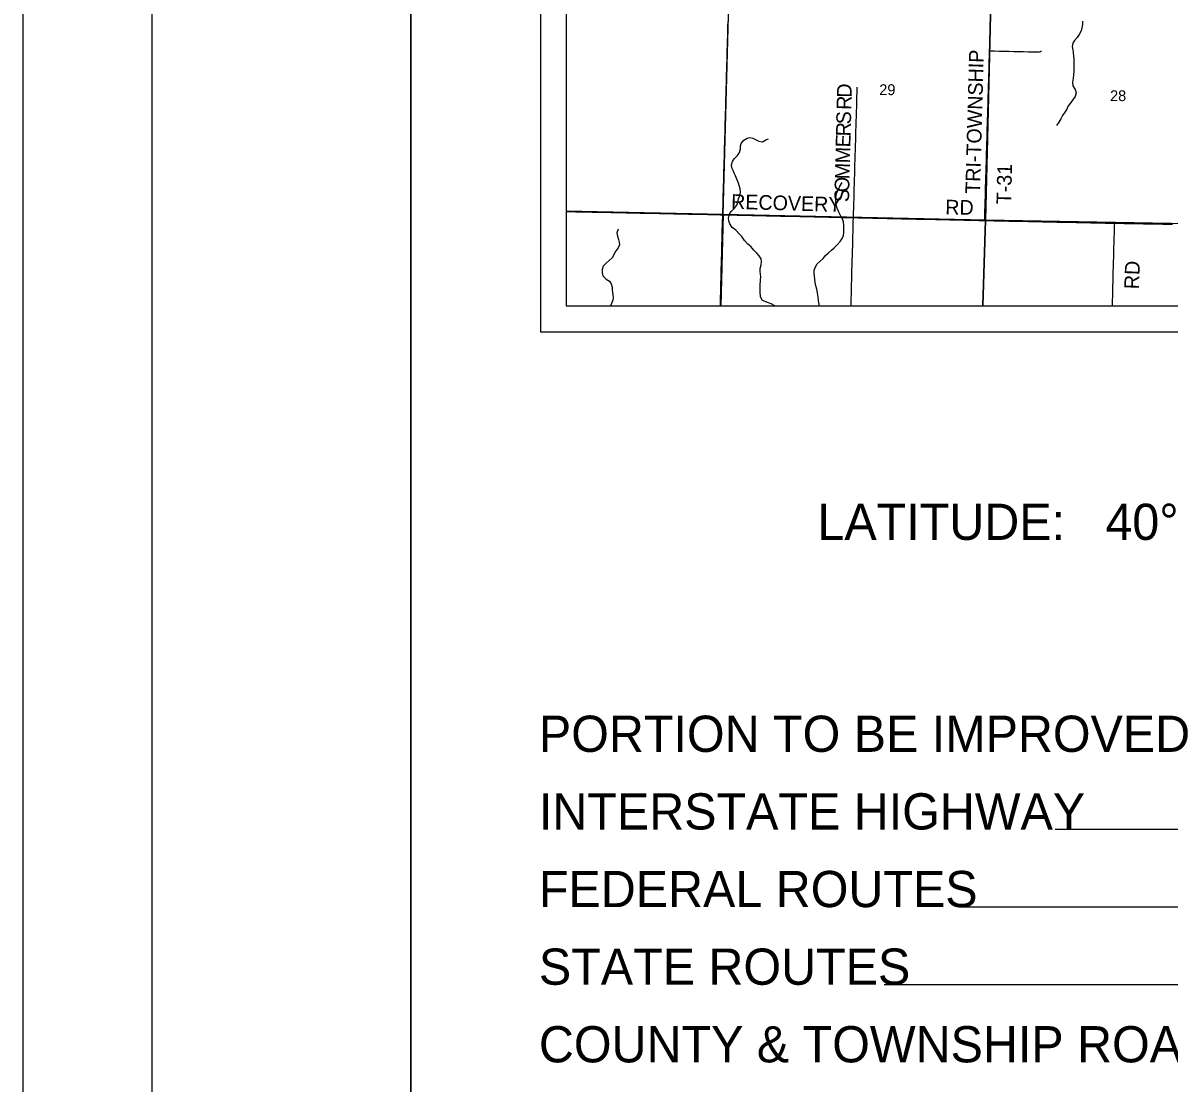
# Model space of a CAD drawing. Extents: x 0 to 34, y 0 to 22.
# Drawn here: x 0 to 4.43, y 11.097 to 15.194 of the extents above; entities that cross this region are included whole.
import ezdxf

# ---------------------------------------------------------------- set-up
doc = ezdxf.new("R2010")
doc.units = 0
for name, color, linetype in [('GM_X_Corporation', 7, 'Continuous'), ('GM_X_County_Road', 7, 'Continuous'), ('GM_X_County_Road_Text', 7, 'Continuous'), ('GM_X_Minor_River', 7, 'Continuous'), ('GM_X_Section_Text', 7, 'Continuous'), ('GM_X_State_Route', 7, 'Continuous'), ('GM_X_Township_Road', 7, 'Continuous'), ('GM_X_Township_Road_Text', 7, 'Continuous'), ('SH_Border', 7, 'Continuous'), ('SH_Cut_Line', 7, 'Continuous'), ('SH_Data', 7, 'Continuous'), ('SH_Text', 7, 'Continuous')]:
    doc.layers.add(name, color=color, linetype=linetype)

msp = doc.modelspace()

# ---------------------------------------------------------------- linework, layer by layer
at = {"layer": 'GM_X_Corporation'}
for points in [[(8.9, 20.9), (2.1, 20.9), (2.1, 14.1), (7.7244, 14.1)], [(4.8738, 16.4249), (4.2697, 16.4379), (3.7682, 16.4494), (3.6948, 16.4501), (3.687, 16.4502), (3.4295, 16.4557), (3.1897, 16.4617), (2.7595, 16.4724), (2.5826, 16.473), (2.4403, 16.4778), (2.4333, 16.478), (2.253, 16.4822), (2.1, 16.485), (2.1, 14.1), (7.7244, 14.1)]]:
    msp.add_lwpolyline(points, dxfattribs=at)
for points in [[(3.745, 15.438), (3.7208, 14.432), (2.7064, 14.4541), (2.7333, 15.4639)], [(4.7451, 15.4188), (4.7262, 14.4138), (3.7208, 14.432), (3.745, 15.438)], [(2.1, 14.4659), (2.1, 14.1), (2.6976, 14.1), (2.7064, 14.4541)], [(2.6976, 14.1), (3.7097, 14.1), (3.7208, 14.432), (2.7064, 14.4541)], [(3.7097, 14.1), (4.7171, 14.1), (4.7262, 14.4138), (3.7208, 14.432)]]:
    msp.add_lwpolyline(points, close=True, dxfattribs=at)
at = {"layer": 'GM_X_County_Road'}
msp.add_lwpolyline([(2.1, 14.4652), (2.1174, 14.4649), (2.136, 14.4645), (2.1547, 14.4641), (2.1733, 14.4637), (2.1865, 14.4634), (2.1997, 14.4631), (2.2183, 14.4628), (2.237, 14.4624), (2.2556, 14.462), (2.2743, 14.4616), (2.2929, 14.4612), (2.3115, 14.4608), (2.3302, 14.4604), (2.3488, 14.4601), (2.3674, 14.4597), (2.3861, 14.4593), (2.4047, 14.4589), (2.4233, 14.4585), (2.442, 14.4581), (2.4606, 14.4577), (2.4792, 14.4574), (2.4979, 14.457), (2.5165, 14.4566), (2.5351, 14.4562), (2.5538, 14.4558), (2.5724, 14.4554), (2.591, 14.4551), (2.6097, 14.4547), (2.6283, 14.4543), (2.647, 14.4539), (2.6656, 14.4535), (2.6842, 14.4531), (2.6946, 14.4529), (2.705, 14.4527), (2.7236, 14.4523), (2.7422, 14.4519), (2.7609, 14.4515), (2.7795, 14.451), (2.7981, 14.4506), (2.8168, 14.4502), (2.8354, 14.4498), (2.854, 14.4494), (2.8727, 14.449), (2.8913, 14.4485), (2.9099, 14.4481), (2.9286, 14.4477), (2.9472, 14.4473), (2.9658, 14.4469), (2.9845, 14.4465), (3.0031, 14.4461), (3.0217, 14.4456), (3.0404, 14.4452), (3.059, 14.4448), (3.0777, 14.4444), (3.0963, 14.444), (3.1149, 14.4436), (3.1336, 14.4432), (3.1522, 14.4427), (3.1708, 14.4423), (3.1895, 14.4419), (3.1998, 14.4417), (3.2102, 14.4415), (3.2288, 14.4411), (3.2475, 14.4406), (3.2661, 14.4402), (3.2847, 14.4398), (3.3034, 14.4394), (3.322, 14.439), (3.3406, 14.4386), (3.3593, 14.4382), (3.3779, 14.4378), (3.3965, 14.4374), (3.4152, 14.437), (3.4338, 14.4365), (3.4524, 14.4361), (3.4711, 14.4357), (3.4897, 14.4353), (3.5083, 14.4349), (3.527, 14.4345), (3.5456, 14.4341), (3.5642, 14.4337), (3.5829, 14.4333), (3.6015, 14.4329), (3.6202, 14.4324), (3.6388, 14.432), (3.6574, 14.4316), (3.6761, 14.4312), (3.6947, 14.4308), (3.7061, 14.4306), (3.7175, 14.4303), (3.7361, 14.4299), (3.7547, 14.4295), (3.7734, 14.4292), (3.792, 14.4288), (3.8106, 14.4284), (3.8293, 14.428), (3.8479, 14.4276), (3.8665, 14.4272), (3.8852, 14.4268), (3.9038, 14.4265), (3.9224, 14.4261), (3.9411, 14.4257), (3.9597, 14.4253), (3.9783, 14.4249), (3.997, 14.4245), (4.0156, 14.4241), (4.0343, 14.4238), (4.0529, 14.4234), (4.0715, 14.423), (4.0902, 14.4226), (4.1088, 14.4222), (4.1274, 14.4218), (4.1461, 14.4214), (4.1647, 14.4211), (4.1833, 14.4207), (4.2016, 14.4203), (4.2199, 14.4199), (4.2385, 14.4196), (4.2572, 14.4192), (4.2758, 14.4189), (4.2945, 14.4186), (4.3131, 14.4183), (4.3317, 14.4179), (4.3504, 14.4176), (4.369, 14.4173), (4.3877, 14.4169), (4.4063, 14.4166), (4.4249, 14.4163), (4.4436, 14.416)], dxfattribs=at)
at = {"layer": 'GM_X_Minor_River'}
for points in [[(4.0956, 15.2006), (4.0957, 15.1885), (4.0935, 15.1748), (4.0909, 15.1635), (4.083, 15.1489), (4.0755, 15.138), (4.065, 15.1261), (4.058, 15.1153), (4.0561, 15.1024), (4.0578, 15.0894), (4.0591, 15.0799), (4.0606, 15.0651), (4.0615, 15.0533), (4.062, 15.0434), (4.0622, 15.0331), (4.0626, 15.0168), (4.0623, 15.0069), (4.0609, 14.9933), (4.0591, 14.9804), (4.0568, 14.9645), (4.058, 14.9512), (4.0672, 14.9369), (4.0714, 14.9239), (4.0673, 14.91), (4.0571, 14.895), (4.0474, 14.8827), (4.0396, 14.873), (4.0347, 14.861), (4.0269, 14.8494), (4.0186, 14.8359), (4.0115, 14.8239), (4.0036, 14.81), (3.9946, 14.7973)], [(2.9069, 14.1), (2.906, 14.1008), (2.8922, 14.1087), (2.8786, 14.1139), (2.8684, 14.1168), (2.8587, 14.1212), (2.8507, 14.1358), (2.8492, 14.1548), (2.8495, 14.1666), (2.8494, 14.1784), (2.8514, 14.2026), (2.8517, 14.2125), (2.8515, 14.2231), (2.8502, 14.233), (2.8501, 14.2452), (2.8539, 14.2592), (2.8545, 14.2717), (2.8536, 14.2816), (2.8463, 14.2939), (2.8374, 14.304), (2.8255, 14.3152), (2.8137, 14.3299), (2.8018, 14.3386), (2.7885, 14.3537), (2.7782, 14.3687), (2.7686, 14.3788), (2.7556, 14.3928), (2.7418, 14.4033), (2.7327, 14.4179), (2.7291, 14.4287), (2.7271, 14.4397), (2.7316, 14.4548), (2.7379, 14.4653), (2.7496, 14.4768), (2.7601, 14.4899), (2.763, 14.4997), (2.7656, 14.5144), (2.772, 14.5291), (2.7738, 14.5405), (2.7725, 14.5523), (2.7701, 14.5618), (2.7654, 14.5748), (2.7601, 14.5901), (2.7539, 14.6036), (2.7496, 14.6139), (2.7453, 14.6235), (2.7406, 14.6339), (2.739, 14.6453), (2.7427, 14.6581), (2.7486, 14.6686), (2.7614, 14.682), (2.7704, 14.6936), (2.7741, 14.7079), (2.774, 14.7186), (2.7765, 14.7284), (2.7859, 14.7403), (2.799, 14.7488), (2.8097, 14.7516), (2.8217, 14.7486), (2.8319, 14.7439), (2.8446, 14.7364), (2.8586, 14.7338), (2.872, 14.7418), (2.882, 14.7458)], [(3.0782, 14.1), (3.0776, 14.1076), (3.0753, 14.1205), (3.0733, 14.135), (3.0714, 14.1506), (3.0683, 14.1651), (3.0652, 14.1781), (3.0628, 14.1911), (3.0612, 14.2044), (3.0592, 14.2147), (3.058, 14.2269), (3.059, 14.2382), (3.0638, 14.2514), (3.0701, 14.2627), (3.081, 14.2738), (3.0934, 14.2834), (3.1035, 14.2965), (3.114, 14.305), (3.126, 14.3161), (3.1356, 14.3242), (3.1469, 14.3361), (3.1594, 14.3491), (3.1668, 14.3603), (3.1713, 14.3728), (3.1727, 14.3838), (3.1729, 14.3959), (3.1725, 14.4107), (3.1717, 14.4248), (3.1682, 14.4366), (3.1619, 14.4467), (3.1532, 14.4624), (3.1471, 14.4774), (3.1436, 14.4904), (3.1423, 14.5006), (3.1422, 14.5109), (3.1437, 14.5268), (3.1466, 14.5381), (3.1534, 14.5532), (3.1578, 14.5637), (3.166, 14.5768)], [(2.3009, 14.3964), (2.296, 14.3824), (2.298, 14.3702), (2.3019, 14.3568), (2.3051, 14.3469), (2.3056, 14.3366), (2.3008, 14.3246), (2.2887, 14.3093), (2.2843, 14.298), (2.2775, 14.286), (2.2663, 14.2756), (2.2547, 14.266), (2.2427, 14.2545), (2.239, 14.2416), (2.2395, 14.2291), (2.2418, 14.2169), (2.2548, 14.2041), (2.2675, 14.1962), (2.2734, 14.1862), (2.2773, 14.1728), (2.2781, 14.1621), (2.2787, 14.1526), (2.2804, 14.1431), (2.2809, 14.1332), (2.2807, 14.1222), (2.2754, 14.1094), (2.2706, 14.1)]]:
    msp.add_lwpolyline(points, dxfattribs=at)
at = {"layer": 'GM_X_State_Route'}
msp.add_lwpolyline([(2.6957, 14.1), (2.6961, 14.1145), (2.6966, 14.1331), (2.6971, 14.1517), (2.6976, 14.1704), (2.6981, 14.189), (2.6985, 14.2076), (2.699, 14.2263), (2.6995, 14.2449), (2.7, 14.2635), (2.7005, 14.2822), (2.701, 14.3008), (2.7015, 14.3194), (2.702, 14.3381), (2.7024, 14.3567), (2.7029, 14.3753), (2.7034, 14.394), (2.7039, 14.4126), (2.7044, 14.4312), (2.7047, 14.442), (2.705, 14.4527), (2.7055, 14.4713), (2.706, 14.49), (2.7065, 14.5086), (2.707, 14.5272), (2.7076, 14.5459), (2.7081, 14.5645), (2.7086, 14.5832), (2.7091, 14.6018), (2.7097, 14.6204), (2.7102, 14.6391), (2.7107, 14.6577), (2.7112, 14.6763), (2.7117, 14.695), (2.7123, 14.7136), (2.7128, 14.7322), (2.7133, 14.7509), (2.7138, 14.7695), (2.7144, 14.7881), (2.7149, 14.8068), (2.7154, 14.8254), (2.7159, 14.844), (2.7164, 14.8627), (2.7169, 14.8813), (2.7175, 14.8999), (2.718, 14.9186), (2.7185, 14.9372), (2.7188, 14.9474), (2.7191, 14.9577), (2.7196, 14.9763), (2.7201, 14.9949), (2.7206, 15.0136), (2.7212, 15.0322), (2.7217, 15.0508), (2.7222, 15.0695), (2.7227, 15.0881), (2.7232, 15.1067), (2.7238, 15.1254), (2.7243, 15.144), (2.7248, 15.1626), (2.7253, 15.1813), (2.7259, 15.1999)], dxfattribs=at)
at = {"layer": 'GM_X_Township_Road'}
for points in [[(3.7175, 14.4303), (3.718, 14.4489), (3.7185, 14.4676), (3.7191, 14.4862), (3.7196, 14.5048), (3.7202, 14.5235), (3.7207, 14.5421), (3.7212, 14.5608), (3.7218, 14.5794), (3.7223, 14.598), (3.7229, 14.6167), (3.7234, 14.6353), (3.7239, 14.6539), (3.7245, 14.6726), (3.725, 14.6912), (3.7256, 14.7098), (3.7261, 14.7285), (3.7266, 14.7471), (3.7272, 14.7657), (3.7277, 14.7844), (3.7283, 14.803), (3.7288, 14.8216), (3.7294, 14.8403), (3.7299, 14.8589), (3.7305, 14.8775), (3.731, 14.8962), (3.7315, 14.9148), (3.7318, 14.9248), (3.7321, 14.9347), (3.7327, 14.9534), (3.7332, 14.972), (3.7337, 14.9906), (3.7342, 15.0093), (3.7348, 15.0279), (3.7353, 15.0465), (3.7358, 15.0652), (3.7361, 15.0755), (3.7364, 15.0859), (3.737, 15.1045), (3.7372, 15.1146), (3.7375, 15.1247), (3.7379, 15.1361), (3.7382, 15.1474), (3.7387, 15.166), (3.739, 15.1764), (3.7393, 15.1869), (3.7398, 15.2055)], [(3.7364, 15.0859), (3.7551, 15.0855), (3.7737, 15.0851), (3.7923, 15.0848), (3.811, 15.0844), (3.8296, 15.084), (3.8482, 15.0836), (3.8669, 15.0832), (3.8855, 15.0828), (3.9041, 15.0825), (3.9169, 15.0822), (3.9297, 15.0819), (3.9336, 15.0838), (3.9367, 15.0865)], [(3.2008, 14.1), (3.201, 14.1084), (3.2015, 14.1271), (3.2021, 14.1457), (3.2026, 14.1643), (3.2031, 14.183), (3.2036, 14.2016), (3.2041, 14.2202), (3.2046, 14.2389), (3.2051, 14.2575), (3.2056, 14.2762), (3.2062, 14.2948), (3.2067, 14.3134), (3.2072, 14.3321), (3.2077, 14.3507), (3.2082, 14.3693), (3.2087, 14.388), (3.2092, 14.4066), (3.2097, 14.424), (3.2102, 14.4415), (3.2107, 14.4601), (3.2113, 14.4787), (3.2118, 14.4974), (3.2124, 14.516), (3.2129, 14.5346), (3.2135, 14.5533), (3.214, 14.5719), (3.2146, 14.5905), (3.2151, 14.6092), (3.2157, 14.6278), (3.2162, 14.6464), (3.2167, 14.6651), (3.2173, 14.6837), (3.2178, 14.7024), (3.2184, 14.721), (3.2189, 14.7396), (3.2195, 14.7583), (3.22, 14.7769), (3.2206, 14.7955), (3.2211, 14.8142), (3.2217, 14.8328), (3.2222, 14.8514), (3.2228, 14.8701), (3.2233, 14.8887), (3.2239, 14.9073), (3.2244, 14.926), (3.2247, 14.9361), (3.225, 14.9462)], [(4.2111, 14.1), (4.2112, 14.1024), (4.2117, 14.121), (4.2122, 14.1397), (4.2127, 14.1583), (4.2132, 14.1769), (4.2137, 14.1956), (4.2142, 14.2142), (4.2147, 14.2328), (4.2153, 14.2515), (4.2158, 14.2701), (4.2163, 14.2887), (4.2168, 14.3074), (4.2173, 14.326), (4.2178, 14.3446), (4.2183, 14.3633), (4.2188, 14.3819), (4.2194, 14.4005), (4.2196, 14.4102), (4.2199, 14.4199)]]:
    msp.add_lwpolyline(points, dxfattribs=at)
at = {"layer": 'SH_Border'}
for points in [[(0.5, 21.5), (1.5, 21.5), (1.5, 0.5), (0.5, 0.5)], [(1.5, 21.5), (33.5, 21.5), (33.5, 0.5), (1.5, 0.5)]]:
    msp.add_lwpolyline(points, close=True, dxfattribs=at)
at = {"layer": 'SH_Cut_Line'}
msp.add_lwpolyline([(0, 0), (34, 0), (34, 22), (0, 22)], close=True, dxfattribs=at)
at = {"layer": 'SH_Data'}
for p, q in [((2, 21), (2, 14)), ((2.1, 20.9), (2.1, 14.1)), ((2.1, 20.9), (2.1, 14.1)), ((2.1, 14.1), (8.9, 14.1)), ((2.1, 14.1), (2.1, 14.1)), ((2.1, 14.1), (8.9, 14.1)), ((2.1, 14.1), (2.1, 14.1)), ((2, 14), (9, 14)), ((7.7, 12.0767), (3.9895, 12.0767)), ((7.7, 11.7767), (3.6192, 11.7767)), ((7.7, 11.4767), (3.3288, 11.4767))]:
    msp.add_line(p, q, dxfattribs=at)

# ---------------------------------------------------------------- texts
at = {"layer": 'GM_X_County_Road_Text'}
for s, rotation, p in [('RECOVERY', 358.3489, (2.7367, 14.4756)), ('RD', 359.0118, (3.5647, 14.4539))]:
    msp.add_text(s, height=0.05682, rotation=rotation, dxfattribs=at).set_placement(p)
at = {"layer": 'GM_X_Section_Text'}
for s, p in [('29', (3.3101, 14.915)), ('28', (4.2022, 14.8917))]:
    msp.add_text(s, height=0.04186, rotation=0, dxfattribs=at).set_placement(p)
at = {"layer": 'GM_X_Township_Road_Text'}
for s, height, rotation, p in [('TRI-TOWNSHIP', 0.056818, 88.4635, (3.6994, 14.5329)), ('D', 0.0568, 89.1826, (3.2029, 14.9047)), ('R', 0.0568, 88.5876, (3.2017, 14.8574)), ('S', 0.0568, 88.5602, (3.2003, 14.8016)), ('R', 0.0568, 88.5616, (3.1992, 14.7549)), ('E', 0.0568, 88.5622, (3.1981, 14.7124)), ('M', 0.0568, 88.5612, (3.1965, 14.6508)), ('M', 0.0568, 88.56, (3.195, 14.5891)), ('T-31', 0.05682, 88.5843, (3.8196, 14.4925)), ('O', 0.0568, 88.5625, (3.1937, 14.5392)), ('S', 0.0568, 88.5602, (3.1928, 14.5008)), ('RD', 0.05682, 88.0252, (4.3136, 14.1641))]:
    msp.add_text(s, height=height, rotation=rotation, dxfattribs=at).set_placement(p)
at = {"layer": 'SH_Text'}
for s, p in [('LATITUDE:   40°26\'13" N    LONGITUDE:   84°22\'26" W', (3.071, 13.1959)), ('PORTION TO BE IMPROVED', (1.9944, 12.3767)), ('INTERSTATE HIGHWAY', (1.9944, 12.0767)), ('FEDERAL ROUTES', (1.9944, 11.7767)), ('STATE ROUTES', (1.9944, 11.4767)), ('COUNTY & TOWNSHIP ROADS', (1.9944, 11.1767))]:
    msp.add_text(s, height=0.14, dxfattribs=at).set_placement(p)

doc.saveas('drawing.dxf')
